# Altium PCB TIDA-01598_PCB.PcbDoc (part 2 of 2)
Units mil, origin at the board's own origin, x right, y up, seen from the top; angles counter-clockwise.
Board outline 5000 x 4300 mil, 4 copper layers (Top Layer, Power, Ground, Bottom Layer), stack 61.6 mil thick; 99 components, 31 nets, 235 pads, 61 vias.
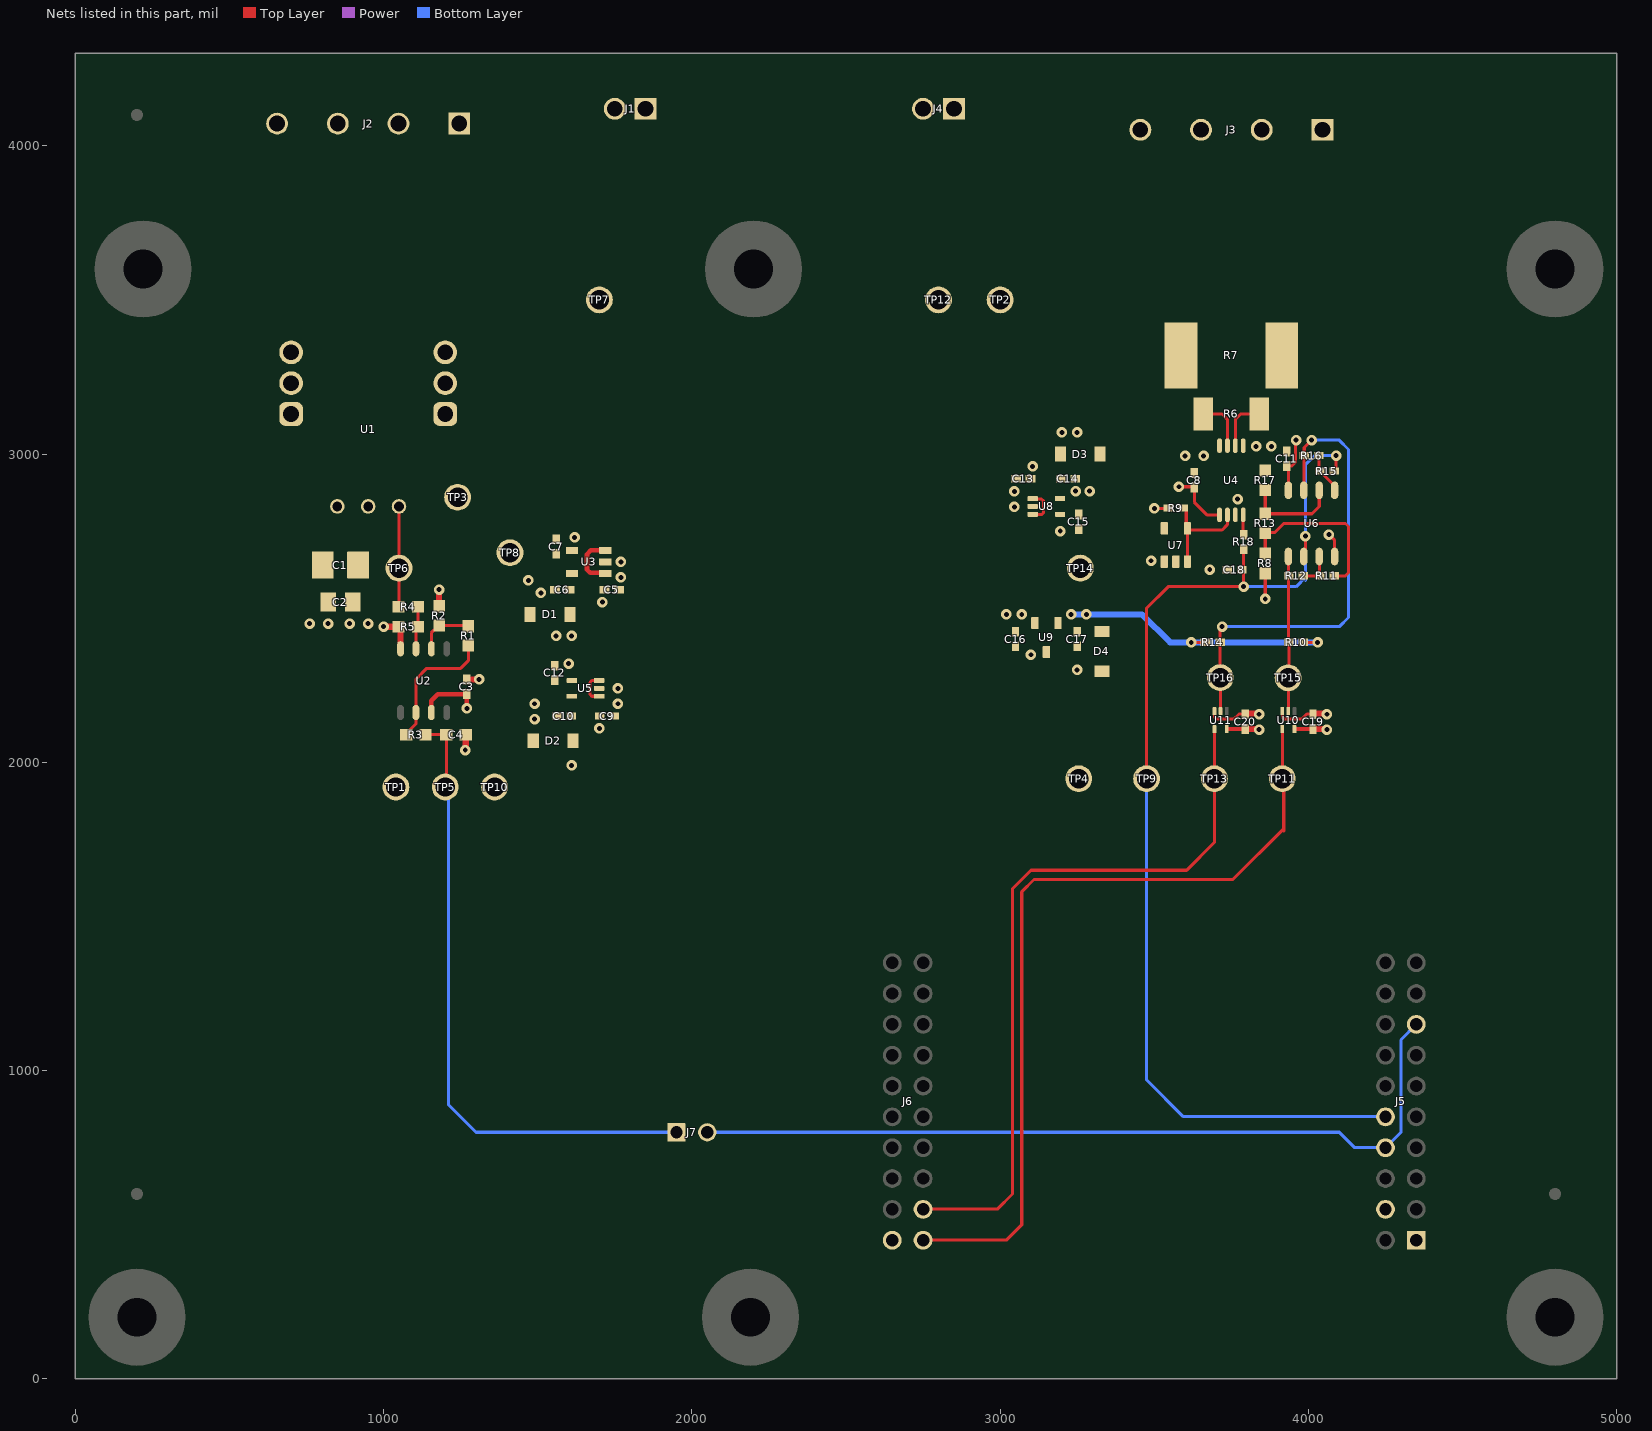
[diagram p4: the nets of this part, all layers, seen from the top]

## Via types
v1: diameter 34, hole 16, Top Layer to Bottom Layer, tented top, 61 vias

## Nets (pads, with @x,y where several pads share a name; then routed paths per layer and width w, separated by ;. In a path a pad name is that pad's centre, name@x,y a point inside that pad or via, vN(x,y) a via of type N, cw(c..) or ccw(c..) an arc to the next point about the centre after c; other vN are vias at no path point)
3V3_DIG: C17.1 D4.1 J5.1 R10.2 R14.2 U9.1 | length 939.2
  Top Layer w10: v1(3620,2388.9) R14.2@3666.38,2388.9 ; R10.2@3983.62,2388.9 v1(4030,2388.9)
  Power w10: v1(4030,2388.9) v1@4040,2388.9
  Bottom Layer w20: v1@3230,2475 3235,2480 v1(3280,2480) 3460,2480 3551.1,2388.9 v1(3620,2388.9) ; v1@3625,2385 3628.9,2388.9 v1(4030,2388.9)
  other v1: 3230,2480
3V3_HALL: C3.1 C10.1 D2.1 TP10.1 U2.7 U5.5 | length 205.2
  Top Layer w15: U2.7@1155,2165 1155,2200 1176.38,2221.38 C3.1@1270,2221.38 v1(1270,2175)
  other v1: 1610,1990
3V3_INA: C8.1 C11.1 C14.1 C19.1 C20.1 D3.1 R8.2 R9.2 TP14.1 U4.5 U6.8 U8.5 U10.5 U11.5 | length 733.8
  Top Layer w10: v1(3500,2823.9) R9.2@3556.38,2823.9 ; v1(3580,2893.9) 3626.38,2893.9 3630,2890.28 3630,2843.9 3672.2,2801.69 U4.5@3711.61,2801.69 ; v1(3860,2530) R8.2@3860,2613.5 R8.2@3860,2615 ; U6.8@3935,2882.28 3935,2956.38 C11.1@3930,2961.38 3946.38,2961.38 3957.76,2972.76 3957.76,3042.76 v1(3960,3045)
  Top Layer w12: U11.5@3734.69,2107.87 3794.13,2107.87 C20.1@3795,2107 ; U10.5@3954.69,2107.87 4014.13,2107.87 C19.1@4015,2107
  Top Layer w20: C20.1@3795,2108.38 v1@3838.62,2108.38 ; C19.1@4015,2108.38 v1@4058.62,2108.38
  other v1: 3840,2105.9 4060,2105.9 3200,3070 3250,3070
5V_HALL: C1.1 C2.1 C6.1 D1.1 TP8.1 U1.9 U3.5
  other v1: 1560,2410 1610,2410 760,2450 820,2450
6V_HALL_VIN: C5.1 C9.1 J1.2 TP7.1 U3.1 U3.3 U5.1 U5.3 | length 281.9
  Top Layer w10: U5.1@1699.29,2214.41 1675.59,2214.37 1669.68,2220.28 1669.68,2259.65 1675.59,2265.56 U5.3@1699.29,2265.59
  Top Layer w15: U3.3@1719.13,2687.4 1672.4,2687.4 1660,2675 1660,2625 1670,2615 U3.1@1720,2615
  other v1: 1700,2109.96 1710,2519.96
6V_VIN: C13.1 C16.1 J4.2 TP12.1 U8.1 U8.3 U9.2 | length 110.5
  Top Layer w10: U8.3@3107.09,2803.31 3134.41,2803.31 3140,2808.9 3140,2848.9 3134.41,2854.49 U8.1@3107.09,2854.49
  other v1: 3020,2480 3070,2480 3105,2960
GND: C1.2 C2.2 C3.2 C4.2 C5.2 C6.2 C7.2 C8.2 C9.2 C10.2 C11.2 C12.2 C13.2 C14.2 C15.2 C16.2 C17.2 C18.2 C19.2 C20.2 D1.2 D2.2 D3.2 D4.2 J1.1 J4.1 J5.22 J6.20 R2.1 R5.1 R17.2 TP1.1 TP2.1 TP3.1 TP4.1 U1.8 U2.4 U3.2 U4.1 U4.4 U4.7 U5.2 U6.4 U7.1 U7.2 U7.5 U8.2 U9.3 U10.3 U11.3 | length 727.5
  Top Layer w10: U11.3@3695.31,2166.13 3695.31,2146.68 3701.93,2140.07 3758.07,2140.07 3775,2157 C20.2@3795,2157 ; U10.3@3915.31,2166.13 3915.31,2146.68 3921.93,2140.07 3978.07,2140.07 3995,2157 C19.2@4015,2157 ; v1(4066.42,2738.62) 4085,2720 U6.4@4085,2667.72
  Top Layer w20: v1(1000,2440) R5.1@1048.5,2440 ; R5.1@1050,2440 1055,2435 U2.4@1055,2368.35 ; R2.1@1180,2506.5 v1(1180,2560) ; v1@1266.5,2041.5 C4.2@1266.5,2090 ; C3.2@1269,2269 v1(1310,2269) ; C3.2@1270,2268.62 v1@1308.62,2268.62 ; C20.2@3795,2158.38 v1@3838.62,2158.38 ; C19.2@4015,2158.38 v1@4058.62,2158.38
  other v1: 1265,2040 1490,2140 3840,2155.9 4060,2155.9 1490,2190 1760,2189.96 1760,2239.96 3250,2300 1600,2319.96 3100,2348.9 890,2450 950,2450 1510,2550 1470,2590 1770,2599.96 3680,2625 1770,2649.96 3490,2653.9 1620,2729.96 3195,2750 3046.38,2828.9 3770,2853.9 3046.38,2878.9 3245,2880 3290,2880 3600,2993.9 3660,2993.9 3830,3025 3880,3025
NetC7_1: C7.1 U3.4
NetC12_1: C12.1 U5.4
NetC15_1: C15.1 U8.4
NetJ2_1: J2.1 J2.2 U1.4 U1.5 U1.6
NetJ2_3: J2.3 J2.4 U1.1 U1.2 U1.3
NetJ3_1: J3.1 J3.2 R6.2 R7.2 U4.2 | length 170.5
  Top Layer w10: U4.2@3762.8,3027.2 3762.8,3112.8 3780,3130 R6.2@3840.55,3130
NetJ3_3: J3.3 J3.4 R6.1 R7.1 U4.3 | length 170.5
  Top Layer w10: R6.1@3659.45,3130 3720,3130 3737.2,3112.8 U4.3@3737.2,3027.2
NetJ5_8: J5.8 J5.24 J7.2 | length 2662.1
  Bottom Layer w10: J7.2@2050,800 4100,800 4150,750 J5.24@4250,750 4300,800 4300,1100 J5.8@4350,1150
NetR1_1: R1.1 R2.2 U2.2 | length 170.6
  Top Layer w10: U2.2@1155,2368.35 1155,2420 R2.2@1175,2440 ; R2.2@1180,2443.5 1268.5,2443.5 R1.1@1270,2445
NetR1_2: R1.2 R3.1 U2.6 | length 432.4
  Top Layer w10: R3.1@1075,2090 1075,2095 1105,2125 U2.6@1105,2161.65 ; U2.6@1105,2165 1105,2270 1140,2305 1250,2305 1275,2330 R1.2@1275,2378.5
NetR4_1: R4.1 TP6.1 U1.7 | length 337.1
  Top Layer w10: R4.1@1045,2495 1050,2500 TP6.1@1050,2630 U1.7@1050,2830
NetR4_2: R4.2 R5.2 U2.3 | length 139.3
  Top Layer w10: U2.3@1105,2368.35 1105,2435 1111.5,2441.5 R4.2@1111.5,2505
NetR8_1: R8.1 R11.1 R13.2 | length 564.2
  Top Layer w10: R8.1@3860,2670 R8.1@3860,2676.5 R13.2@3860,2743.5 ; R13.2@3860,2745 3890,2745 3920,2775 4120,2775 4130,2765 4130,2615 4120,2605 R11.1@4083.62,2605 R11.1@4080,2605
NetR9_1: R9.1 U4.6 U7.3 U7.4 | length 344.9
  Top Layer w10: R9.1@3603.62,2823.9 3603.62,2761.81 U7.4@3607.4,2758.03 ; U7.3@3607.4,2649.76 U7.3@3607.4,2650.87 U7.4@3607.4,2758.03 ; U4.6@3737.2,2801.69 3737.2,2771.1 3720,2753.9 3611.54,2753.9 U7.4@3607.4,2758.03
NetR10_1: R10.1 R12.2 TP15.1 U6.1 U10.2 | length 532.9
  Top Layer w10: TP15.1@3931,2271 3935,2267 U10.2@3935,2166.13 ; U10.2@3935,2162 U10.2@3935.91,2162.91 ; R10.1@3935,2385 U6.1@3935,2667.72 U6.1@3935,2677.72 ; R10.1@3935.91,2389.53 R10.1@3936.38,2390 3936.38,2260.62 TP15.1@3938,2259
NetR11_2: R11.2 R12.1 U6.3 | length 116
  Top Layer w10: R12.1@3983.62,2605 R11.2@4036.38,2605 4036.38,2666.34 U6.3@4035,2667.72
NetR13_1: R13.1 R17.1 U6.6 | length 312.5
  Top Layer w10: R17.1@3860,2882.01 R13.1@3860,2806.5 4011.5,2806.5 4035,2830 U6.6@4035,2882.28
NetR14_1: R14.1 R16.2 TP16.1 U6.7 U11.2 | length 1567.9
  Top Layer w10: TP16.1@3706,2261 3713.62,2268.62 R14.1@3713.62,2390 3713.62,2433.62 v1(3720,2440) ; U11.2@3715,2162 U11.2@3715.91,2162.91 ; U11.2@3715,2166.13 TP16.1@3715,2272 ; U6.7@3985,2882.28 R16.2@3985,2993.62 ; R16.2@3986.38,2995 3986.38,3021.38 v1(4010,3045)
  Bottom Layer w10: v1@3715,2440 v1(3720,2440) 4100,2440 4130,2470 4130,3015 4100,3045 v1(4010,3045)
NetR15_2: R15.2 R16.1 U6.5 | length 134
  Top Layer w10: R16.1@4033.62,2995 4033.62,2947.76 R15.2@4036.38,2945 4085,2896.38 U6.5@4085,2882.28
NetR18_1: R18.1 U4.8 | length 64.8
  Top Layer w10: U4.8@3788.39,2802.8 3788.39,2740.24 R18.1@3790,2738.62
OUT_A: J6.40 TP11.1 U10.4 | length 2691
  Top Layer w10: J6.40@2750,450.86 2750.86,450 3020,450 3070,500 3070,1580 3110,1620 3755,1620 3920,1785 ; TP11.1@3915,1942 3915.31,1942.32 U10.4@3915.31,2107.87 ; 3920,1778 3920,1785 ; TP11.1@3920,1947 3920,1785
OUT_B: J6.39 TP13.1 U11.4 | length 2390.5
  Top Layer w10: J6.39@2750,550.86 2990.86,550.86 3040,600 3040,1590 3100,1650 3605,1650 3695,1740 TP13.1@3695,1942 ; TP13.1@3695,1947 TP13.1@3695,1942 ; U11.4@3695.31,2107.87 3695.31,1942.32 TP13.1@3695,1942
OUT_HALL: C4.1 J7.1 R3.2 TP5.1 | length 2050.5
  Top Layer w10: R3.2@1136.5,2090 1200,2090 C4.1@1203.5,2086.5 ; TP5.1@1198.5,1921.46 TP5.1@1200,1919.96 ; TP5.1@1200,1925 1203.5,1928.5 C4.1@1203.5,2086.5 ; C4.1@1203.5,2090 C4.1@1203.5,2086.5 ; C4.1@1205,2085 C4.1@1203.5,2086.5
  Bottom Layer w10: TP5.1@1200,1919.96 1210,1909.96 1210,890 1300,800 J7.1@1950,800
OUT_INA: C18.1 J5.25 R15.1 R18.2 TP9.1 U6.2 | length 3641.9
  Top Layer w10: TP9.1@3474,1940 3475,1941 3475,2500 3545,2570 v1(3790,2570) R18.2@3790,2691.38 ; U6.2@3990,2675 v1(3990,2733.9) ; R15.1@4080,2945 4090,2955 v1(4090,2995)
  Bottom Layer w10: TP9.1@3477,1948 3475,1946 3475,970 3594.14,850.86 J5.25@4250,850.86 ; v1(3790,2570) 3960,2570 3990,2600 ; 3990,2590 3990,2600 ; v1(4090,2995) 4020,2995 3990,2965 3990,2600
pads on no net: FID1.1 FID2.1 FID3.1 H1.1 H2.1 H3.1 H4.1 H5.0 H6.0 H7.0 H8.0 H9.1 H10.0 H11.1 H12.0 J5.2 J5.3 J5.4 J5.5 J5.6 J5.7 J5.9 J5.10 J5.21 J5.23 J5.26 J5.27 J5.28 J5.29 J5.30 J6.11 J6.12 J6.13 J6.14 J6.15 J6.16 J6.17 J6.18 J6.19 J6.31 J6.32 J6.33 J6.34 J6.35 J6.36 J6.37 J6.38 U2.1 U2.5 U2.8 U10.1 U11.1

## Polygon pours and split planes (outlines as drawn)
NetJ2_1 on Top Layer "TOP_LAYER_NETJ2_1_P134" (solid, remove dead copper, pour order 134): 999.96,4239.96 1445.04,4239.96 1470,4215 1470,3075 1444.96,3049.96 995.04,3049.96 960,3085 960,4200
NetJ2_3 on Top Layer "TOP_LAYER_NETJ2_3_P132" (solid, remove dead copper, pour order 132): 940,4215 940,3085 904.96,3049.96 485.04,3049.96 455,3080 455,4210 484.96,4239.96 915.04,4239.96
GND on Top Layer "TOP_LAYER_GND_P122" (solid, remove dead copper, pour order 122): 910,2800 910,2870 980,2870 980,2430 870,2430 870,2760
5V_HALL on Top Layer "TOP_LAYER_5V_HALL_P120" (solid, remove dead copper, pour order 120): 850,2430 850,2760 880,2790 880,2870 810,2870 740,2800 740,2430
GND on Top Layer "TOP_LAYER_GND_P108" (solid, remove dead copper, pour order 108): 3740,2873.9 3750,2883.9 3790,2883.9 3800,2873.9 3800,2773.9 3740,2773.9
GND on Top Layer "TOP_LAYER_GND_P106" (solid, remove dead copper, pour order 106): 3921.1,3053.9 3950,3025 3950,2985 3900,2985 3880,2965 3880,2925 3830,2925 3830,2945 3780,2993.9 3780,3053.9
GND on Top Layer "TOP_LAYER_GND_P102" (solid, remove dead copper, pour order 102): 3660,2604.5 3756.77,2604.5 3756.77,2644.5 3660,2644.5
GND on Top Layer "TOP_LAYER_GND_P096" (solid, remove dead copper, pour order 96): 3580,2625 3580,2775 3570,2785 3470,2785 3460,2775 3460,2635 3470,2625
GND on Top Layer "TOP_LAYER_GND_P092" (solid, remove dead copper, pour order 92): 3720,3045 3720,2935 3710,2925 3590,2925 3580,2935 3580,3045 3590,3055 3710,3055
6V_VIN on Top Layer "TOP_LAYER_6V_VIN_P090" (solid, remove dead copper, pour order 90): 3140,2420 3140,2490 3130,2500 3010,2500 3000,2490 3000,2420 3010,2410 3130,2410
3V3_DIG on Top Layer "TOP_LAYER_3V3_DIG_P088" (solid, remove dead copper, pour order 88): 3360,2410 3170,2410 3160,2420 3160,2490 3170,2500 3350,2500 3360,2490
GND on Top Layer "TOP_LAYER_GND_P086" (solid, remove dead copper, pour order 86): 3030,2400 3020,2390 3020,2340 3030,2330 3220,2330 3220,2280 3230,2270 3360,2270 3370,2280 3370,2370 3340,2400
GND on Top Layer "TOP_LAYER_GND_P084" (solid, remove dead copper, pour order 84): 3276.38,2778.9 3176.38,2778.9 3176.38,2728.9 3276.38,2728.9
GND on Top Layer "TOP_LAYER_GND_P082" (solid, remove dead copper, pour order 82): 3230,3030 3220,3020 3220,2870 3230,2860 3340,2860 3350,2870 3350,3030
GND on Top Layer "TOP_LAYER_GND_P080" (solid, remove dead copper, pour order 80): 3026.38,2798.9 3026.38,2938.9 3126.38,2938.9 3126.38,2798.9
NetC15_1 on Top Layer "TOP_LAYER_NETC15_1_P002" (solid, remove dead copper, pour order 2): 3170,2778.9 3276.38,2778.9 3276.38,2828.9 3236.38,2828.9 3226.38,2818.9 3170,2818.9
6V_VIN on Top Layer "TOP_LAYER_6V_VIN_P078" (solid, remove dead copper, pour order 78): 3126.38,2838.9 3086.38,2838.9 3086.38,2978.9 3126.38,2978.9
3V3_INA on Top Layer "TOP_LAYER_3V3_INA_P076" (solid, remove dead copper, pour order 76): 3210,2840 3170,2840 3170,3080 3180,3090 3270,3090 3280,3080 3280,3060 3270,3050 3220,3050 3210,3040
GND on Top Layer "TOP_LAYER_GND_P074" (solid, remove dead copper, pour order 74): 1530,2289.96 1630,2289.96 1630,2339.96 1530,2339.96
GND on Top Layer "TOP_LAYER_GND_P072" (solid, remove dead copper, pour order 72): 1580,2049.96 1580,2200 1570.04,2209.96 1469.96,2209.96 1460,2200 1460,2040 1570.04,2040
GND on Top Layer "TOP_LAYER_GND_P070" (solid, remove dead copper, pour order 70): 1780,2259.96 1780,2140 1770,2130 1680,2129.96 1680,2269.96 1770,2269.96
NetC12_1 on Top Layer "TOP_LAYER_NETC12_1_P068" (solid, remove dead copper, pour order 68): 1630,2289.96 1530,2289.96 1530,2239.96 1570,2239.96 1580,2249.96 1630,2249.96
6V_HALL_VIN on Top Layer "TOP_LAYER_6V_HALL_VIN_P066" (solid, remove dead copper, pour order 66): 1680,2229.96 1720,2229.96 1720,2089.96 1680,2089.96
3V3_HALL on Top Layer "TOP_LAYER_3V3_HALL_P064" (solid, remove dead copper, pour order 64): 1590,2229.96 1630,2230 1640,2220 1640,1980 1630,1970 1590,1970
5V_HALL on Top Layer "TOP_LAYER_5V_HALL_P004" (solid, remove dead copper, pour order 4): 1589.96,2629.96 1630,2629.96 1630,2390 1540,2390 1540,2430 1580,2430 1580,2620
NetC7_1 on Top Layer "TOP_LAYER_NETC7_1_P014" (solid, remove dead copper, pour order 14): 1640,2699.96 1540,2699.96 1540,2649.96 1580,2649.96 1590,2659.96 1640,2659.96
GND on Top Layer "TOP_LAYER_GND_P022" (solid, remove dead copper, pour order 22): 1560,2450 1570.2,2460 1570.2,2599.8 1560,2610 1450,2610 1450,2450
GND on Top Layer "TOP_LAYER_GND_P062" (solid, remove dead copper, pour order 62): 1540,2699.96 1640,2699.96 1640,2749.96 1540,2749.96
GND on Top Layer "Bottom Layer-No Net" (solid, remove dead copper, pour order 140): 1700,2665 1750,2665 1765,2680 1800,2680 1805,2675 1805,2545 1800,2540 1750,2540 1745,2545 1745,2630 1740,2635 1700,2635 1695,2640 1695,2660 1700,2665
6V_HALL_VIN on Top Layer "Bottom Layer-No Net" (solid, remove dead copper, pour order 142): 1740,2625 1690,2625 1685,2620 1685,2500 1690,2495 1730,2495 1735,2500 1735,2620 1740,2625
NetJ3_3 on Top Layer "Bottom Layer-No Net" (solid, remove dead copper, pour order 144): 3740,3650 3690,3600 3690,3165 3690,3080 3685,3075 3395,3075 3265,3205 3150,3320 3150,3830 3150,4200 3180,4230 3710,4230 3740,4200 3740,3650
NetJ3_1 on Top Layer "Bottom Layer-No Net" (solid, remove dead copper, pour order 146): 3760,3650 3810,3600 3810,3080 3815,3075 4315,3075 4335,3095 4350,3110 4350,3165 4350,4205 4320,4235 3780,4235 3760,4215 3760,3650
GND on Ground "GROUND_GND_P006" (solid, remove dead copper, pour order 6): 80,4300 4910,4300 5000,4210 5000,270 4730,0 270,0 0,270 0,4220
3V3_HALL on Power "POWER_3V3_HALL_P126" (solid, remove dead copper, pour order 126): 1640,1875 1640,2330 1620.04,2349.96 864.96,2349.96 850,2335 850,1885 875,1860 1625,1860
5V_HALL on Power "POWER_5V_HALL_P118" (solid, remove dead copper, pour order 118): 1640,2755 1640,2400 1629.96,2389.96 675.04,2389.96 650,2415 650,2730 675,2755
6V_HALL_VIN on Power "POWER_6V_HALL_VIN_P012" (solid, remove dead copper, pour order 12): 1920,4230 1660,4230 1650,4220 1650,2000 1660,1990 1920,1990 1930,2000 1930,4220
3V3_DIG on Power "POWER_3V3_DIG_P136" (solid, remove dead copper, pour order 136): 3160,2488.9 3160,2500 3170,2510 3340,2510 3350,2500 3350,595 3365,580 4420,580 4430,570 4430,340 4420,330 3205,330 3160,375
6V_VIN on Power "POWER_6V_VIN_P138" (solid, remove dead copper, pour order 138): 2925,4230 2675,4230 2660,4215 2660,2010 2680,1990 3120,1990 3140,2010 3140,3080 3120,3100 2960,3100 2940,3120 2940,4215
3V3_INA on Power "Bottom Layer-No Net" (solid, remove dead copper, pour order 148): 3185,3100 3170,3100 3160,3090 3160,2555 3185,2530 3390,2530 3415,2505 3415,2094 3458,2051 4108,2051 4160,2103 4160,2530 4160,3080 4140,3100

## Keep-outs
Keep-Out Layer:
  text ".Layer_Name" at 577,-858.49 h60

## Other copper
Top Layer:
  text ".Layer_Name" at 577,-858.49 h60
Bottom Layer:
  text ".Layer_Name" at 577,-858.49 h60

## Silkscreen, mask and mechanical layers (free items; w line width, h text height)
Top Overlay:
  region: 100,3200 100,2900 200,2900 200,3200
  lines w5: 3720,2490 3820,2490 3820,2706 ; 3820,2705 3830,2715
  lines w10: 550,3648.86 550,3750 550,3865 ; 550,3650 1350,3650 ; 550,3748.86 1350,3748.86 ; 950,3750 950,3865 ; 1350,3648.86 1350,3750 1350,3865 ; 1800,3650 1800,3990 ; 1910,3991.1 1910,3650 1690,3650 ; 2800,3650 2800,3990 ; 2910,3991.1 2910,3650 2690,3650 ; 3350,3628.9 3350,3728.9 ; 3350,3630 4150,3630 ; 3350,3845 3350,3730 4150,3730 4150,3845 ; 3470,2740 3470,2580 4140,2580 4140,2640 ; 3470,2810 3470,3430 ; 3475,3430 4140,3430 4140,2740 ; 3750,3730 3750,3845 ; 1350,3748.86 1350,3748.86 ; 1690,3650 1690,3991.1 1591.1,3991.1 1590,3990 1590,3650 1690,3650 ; 2690,3650 2590,3650 2590,3990 2591.1,3991.1 2690,3991.1 2690,3650 ; 4150,3628.9 4150,3628.9 ; 4150,3628.9 4150,3728.9 ; 4150,3728.9 4150,3728.9 ; 650,2020 650,3630 1320,3630 1320,2020 650,2020
  text "HALL HIGH" at 590,3790 h72.83
  text "HALL LOW" at 990,3790 h72.83
  text "INA LOW" at 3420,3770 h72.83
  text "INA HIGH" at 3810,3770 h72.83
  text "Supply" at 1650,3740 h72.83 r90
  text "GND IN" at 1870,3740 h72.83 r90
  text "Supply" at 2650,3740 h72.83 r90
  text "GND IN" at 2870,3740 h72.83 r90
  text "5V-7V IN" at 1770,3700 h72.83 r90
  text "5V-7V IN" at 2770,3700 h72.83 r90
  text "15A Max Passthrough" at 640,3680 h72.83
  text "15A Max Passthrough" at 3440,3660 h72.83
  text "TIDA-01598" at 4800,1850 h108.27 r90
  text ".Layer_Name" at 577,-858.49 h60
Bottom Overlay:
  text ".Layer_Name" at 577,-858.49 h60
Top Paste:
  text ".Layer_Name" at 577,-858.49 h60
Bottom Paste:
  text ".Layer_Name" at 577,-858.49 h60
Top Solder:
  text ".Layer_Name" at 577,-858.49 h60
  text ".Layer_Name" at 577,-858.49 h60
Bottom Solder:
  text ".Layer_Name" at 577,-858.49 h60
Drill Guide:
  text ".Layer_Name" at 577,-858.49 h60
M1 Board Outline:
  the board outline again, w10
  text ".Layer_Name" at 577,-858.49 h60
M2 Board Dimensions:
  rectangle: 0,-275 125,-150
  rectangle: 125,-400 500,-275
  lines w7: 0,-275 1000,-275 ; 125,-400 125,-150 ; 250,-400 250,-150 ; 500,-400 500,-150 ; 750,-400 750,-150 ; 0,-400 1000,-400 1000,-150 0,-150 0,-400
  text ".Layer_Name" at 577,-858.49 h60
M3 3D STEP Top:
  text ".Layer_Name" at 577,-858.49 h60
M4 3D STEP Bottom:
  text ".Layer_Name" at 577,-858.49 h60
M5 Assembly Top:
  circle w10: c1680,2610 r5
  circle w10: c1710,2215 r5
  circle w10: c3091,2855 r3.16
  circle w10: c3111,2474 r8.25
  circle w10: c3533,2631 r6
  circle w10: c3735,2352 r3
  circle w10: c3956,2353 r6.08
  lines w10: -292,-930.17 6308,-930.17 ; -292,-726.83 6310,-726.83 ; -292,-523.5 -292,-1133.5 3713,-1133.5 6310,-1133.5 6310,-523.5 -291.5,-523.5 -291.5,-1133.5 1284,-1133.5 ; 2173,-1133.5 2173,-523.5 ; 3440,-726.83 3440,-523.5 ; 4280,-726.83 4280,-523.5 ; 4902,-1140 4902,-937.17
  text "COMPONENTS MARKED 'DNP' SHOULD NOT BE POPULATED." at 1153.5,-318.5 h25
  text "ASSEMBLY VARIANT:" at 1153,-434 h25
  text ".VariantName" at 2189,-434 h25
  text "PCB VIEWED FROM TOP SIDE" at -228.5,-655.67 h25
  text "BOARD #:" at 2248,-655.67 h25
  text ".PRJ_Number" at 2793.5,-655.67 h25
  text "REV:" at 3638,-655.67 h25
  text ".PCB_Rev" at 3929.5,-655.67 h25
  text "SVN REV:" at 4476,-655.67 h25
  text ".VersionControl_RevNumber" at 4982,-655.67 h25
  text "TID #:" at 2248,-859 h25
  text ".TID" at 2793.5,-859 h25
  text "PLOT NAME =" at -228.5,-1064.34 h25
  text ".plot_File_Name" at 577,-1064.34 h25
  text "GENERATED    :" at 2250,-1064.34 h25
  text ".Print_Date" at 3119.5,-1064.34 h25
  text ".Print_Time" at 3848.5,-1064.34 h25
  text "TEXAS INSTRUMENTS" at 5113,-1064.34 h25
M6 Assembly Bottom:
  lines w10: -292.5,-727.33 6309.5,-727.33 ; -290.5,-930.67 6309.5,-930.67 ; 1115.5,-1140.5 1115.5,-937.67 ; 1737.5,-727.33 1737.5,-524 ; 2577.5,-727.33 2577.5,-524 ; 3844.5,-1134 3844.5,-524 ; 4733.5,-1134 6309,-1134 6309,-524 -292.5,-524 -292.5,-1134 2304.5,-1134 6309.5,-1134 6309.5,-524
  text "COMPONENTS MARKED 'DNP' SHOULD NOT BE POPULATED." at 6102,-318 h60
  text ".VariantName" at 5058,-434 h60
  text "ASSEMBLY VARIANT:" at 6097,-434 h60
  text ".VersionControl_RevNumber" at 1035.5,-656.17 h60
  text "SVN REV:" at 1541.5,-656.17 h60
  text ".PCB_Rev" at 2088,-656.17 h60
  text "REV:" at 2379.5,-656.17 h60
  text ".PRJ_Number" at 3224,-656.17 h60
  text "BOARD #:" at 3769.5,-656.17 h60
  text "PCB VIEWED FROM BOTTOM SIDE" at 6246,-656.17 h60
  text ".TID" at 3224,-859.5 h60
  text "TID #:" at 3769.5,-859.5 h60
  text "TEXAS INSTRUMENTS" at 904.5,-1064.84 h60
  text ".Print_Time" at 2169,-1064.84 h60
  text ".Print_Date" at 2898,-1064.84 h60
  text "GENERATED    :" at 3767.5,-1064.84 h60
  text ".plot_File_Name" at 5440.5,-1064.84 h60
  text "PLOT NAME =" at 6246,-1064.84 h60
M9 Title Sheet:
  drawing of 57 lines, arcs and shapes, not listed
  text "1" at 739.84,8036.5 h70
  text "2" at 3235.5,8036.5 h70
  text "3" at 5724.84,8036.5 h70
  text "4" at 8231.51,8036.5 h70
  text "5" at 10730.5,8036.5 h70
  text "6" at 13235.5,8036.5 h70
  text "A" at -416.5,6893.5 h70
  text "A" at 14383.5,6893.5 h70
  text "B" at -416.5,4513.5 h70
  text "B" at 14383.5,4513.5 h70
  text "C" at -416.5,2138.5 h70
  text "C" at 14383.5,2138.5 h70
  text "PROJECT TITLE:" at 11343.5,277.5 h45
  text ".PRJ_Title" at 11393.5,144.17 h70
  text "DESIGNED FOR:" at 11343.5,-23.5 h45
  text ".PRJ_Customer" at 11393.5,-163.5 h70
  text "D" at -416.5,-231.5 h70
  text "D" at 14383.5,-231.5 h70
  text "FILE NAME:" at 11343.5,-323.5 h45
  text ".PCB_File_Name_No_Path" at 11393.5,-443.5 h70
  text "Texas Instruments (TI) and/or its licensors do not warrant the accuracy or completeness of this specification" at 6374,-605.34 h45
  text "ENGINEER:" at 11343.5,-613.5 h45
  text "LAYOUT BY:" at 12848.5,-613.5 h45
  text "or any information contained therein. TI and/or its licensors do not warrant that this design will meet" at 6329.01,-718 h45
  text ".PRJ_Engineer" at 11393.5,-768.49 h70
  text ".PCB_Layout" at 12899,-768.49 h70
  text "the specifications, will be suitable for your application or fit for any particular purpose, or will operate in" at 6329.01,-830.67 h45
  text ".Layer_Name" at 577,-858.49 h60
  text "ALTIUM DESIGNER VERSION:" at 12848.5,-923.5 h45
  text "an implementation. TI and/or its licensors do not warrant that the design is production worthy. You should" at 6329.01,-943.33 h45
  text "completely validate and test your design implementation to confirm the system functionality for your application." at 6374,-1056 h45
  text ".print_Scale" at 11393.5,-1056.83 h70
  text ".Application_BuildNumber" at 12899,-1056.83 h70
  text "1" at 739.84,-1263.5 h70
  text "2" at 3235.5,-1263.5 h70
  text "3" at 5724.84,-1263.5 h70
  text "4" at 8231.51,-1263.5 h70
  text "5" at 10730.5,-1263.5 h70
  text "6" at 13235.5,-1263.5 h70
M10 Fab Notes:
  drawing of 189 lines, arcs and shapes, not listed
  text "DESIGN INFORMATION" at 12382.02,6356.17 h60
  text "MIN. TRACK WIDTH:" at 11737.46,6224.05 h60
  text "8" at 12833.7,6224.05 h60
  text "MIL" at 12988.46,6224.05 h60
  text "MIN. CLEARANCE:" at 11737.46,6099.92 h60
  text "0.2" at 12773.7,6099.93 h60
  text "mm" at 12988.46,6099.92 h60
  text "MIN. VIA PAD SIZE:" at 11737.46,5975.8 h60
  text "24" at 12803.71,5975.8 h60
  text "MIL" at 12988.46,5975.8 h60
  text "0.05mm (2MIL)" at 12432.46,5845.9 h60
  text "MINIMUM ANNULAR RING" at 11408.23,5837.67 h60
  text "EXTERNAL" at 13140.46,5837.67 h60
  text "PER" at 11608.23,5727.55 h60
  text "IPC-D-275 CLASS 2 LEVEL C" at 11828.23,5727.54 h60
  text "MIL, HOLES" at 13316.46,5627.07 h60
  text "+/-" at 12924,5618.48 h60
  text "+/-" at 13778,5618.48 h60
  text "REGISTRATION TOLERANCES:" at 11408.23,5617.42 h60
  text "METAL" at 12608,5617.42 h60
  text "5" at 13184.2,5617.42 h60
  text "3" at 14017.2,5617.42 h60
  text "MIL" at 14133.46,5617.42 h60
  text "HOLE SIZE TOLERANCE (UNLESS OTHERWISE SPECIFIED):" at 11408.23,5519.1 h60
  text "+/-" at 13778,5516.23 h60
  text "3" at 14017.2,5515.17 h60
  text "MIL" at 14133.46,5515.17 h60
  text "MATERIAL:" at 11333.46,5377.52 h60
  text "FR-4 High Tg" at 12319.9,5249 h60
  text "X" at 12175.46,5241.01 h60
  text "FR-408" at 11754.46,5236.49 h60
  text "OTHER" at 13242.46,5236.49 h60
  text "62 MIL (1.6mm) +/-10%" at 12074.56,5093.46 h60
  text "X" at 11954.46,5091.01 h60
  text "THICKNESS:" at 11408.23,5085.24 h60
  text "OTHER" at 13359.46,5085.24 h60
  text "TOLERANCE:" at 11408.23,4946.92 h60
  text "X" at 12256.46,4946.92 h60
  text "ANSI IPC-6012 TYPE 3 CLASS 2" at 12434.48,4946.92 h60
  text "OTHER +/-" at 12434.46,4802.73 h60
  text "BOW & TWIST:" at 11408.23,4657.54 h60
  text "X" at 12256.46,4657.54 h60
  text "ANSI IPC-6012 TYPE 3 CLASS 2" at 12434.48,4657.54 h60
  text "OTHER +/-" at 12434.46,4510.85 h60
  text "DRILLING:" at 11333.46,4380.23 h60
  text "NC_DRILL FILES" at 13094.46,4275.04 h60
  text "REFERENCE:" at 11408.23,4271.1 h60
  text "X" at 12065.46,4271.01 h60
  text "AS SHOWN" at 12243.46,4271.1 h60
  text "X" at 12966.46,4271.1 h60
  text "OTHER" at 13392.46,4128.85 h60
  text "PTH COPPER THICKNESS:" at 11407.91,4125.32 h60
  text "X" at 12547.14,4125.32 h60
  text "20-30 um" at 12675.14,4125.32 h60
  text "BOARD FINISH:" at 11333.46,3977.73 h60
  text "SILKSCREEN:" at 11488.68,3867.6 h60
  text "X" at 12446.46,3867.6 h60
  text "TOP" at 12563.46,3867.6 h60
  text "X" at 12956.46,3867.6 h60
  text "BOTTOM" at 13074.46,3867.6 h60
  text "SILKSCREEN COLOR:" at 11488.68,3712.41 h60
  text "X" at 12445.46,3712.41 h60
  text "WHITE" at 12563.46,3712.41 h60
  text "OTHER" at 13074.46,3712.41 h60
  text "X" at 12576.46,3568.96 h60
  text "GREEN" at 12694.46,3568.96 h60
  text "OTHER" at 13312.46,3568.96 h60
  text "SOLDER RESIST COLOR:" at 11488.68,3562.1 h60
  text "X" at 12576.46,3414.71 h60
  text "MATTE" at 12694.46,3414.71 h60
  text "SEMI-GLOSS" at 13312,3414.07 h60
  text "IMMERSION GOLD (ENIG)" at 12394.46,3241.94 h60
  text "ENEPIG" at 13732,3234.72 h60
  text "SURFACE FINISH:" at 11333.46,3233.72 h60
  text "X" at 12216.46,3233.72 h60
  text "IMM. TIN/SILVER OR EQUIV" at 11663,3096.4 h60
  text "OTHER" at 13094.46,3092.47 h60
  text "ARRAY/PANEL:" at 11333.46,2937.09 h60
  text "CUT AND TRIM PER M1 BOARD OUTLINE" at 12394.46,2928.87 h60
  text "N.C. ROUTE" at 12394.46,2792.9 h60
  text "X" at 13082.46,2792.9 h60
  text "V. SCORE" at 13260.46,2792.9 h60
  text "CERTIFICATION:" at 11333.46,2663.77 h60
  text "MATERIALS AND WORKMANSHIP FOR ALL PCBS" at 12058.46,2663.77 h60
  text "TO MEET OR EXCEED THE REQUIREMENTS OF:" at 12058.46,2569.71 h60
  text "X" at 11695.97,2441.08 h60
  text "ANSI IPC-A-600F CLASS ->" at 11823.96,2441.08 h60
  text "X" at 13471.97,2441.08 h60
  text "2" at 13581.96,2441.08 h60
  text "1" at 13266.96,2439.58 h60
  text "3" at 13935.96,2439.58 h60
  text "X" at 12507.97,2293.39 h60
  text "RoHS" at 12635.96,2293.39 h60
  text "OTHER" at 13280.36,2293.39 h60
  text "PER ORDER" at 13677.42,2293.39 h60
  text "ALL BOARDS MUST MEET OR EXCEED UL94-V0 REQUIREMENTS." at 11361,2139.57 h60
  text "PCB MUST BEAR THE UL94V-0 UL REGISTERED MATERIAL ID NUMBER" at 11361,2023.5 h60
  text "ADDITIONAL REQUIREMENTS:" at 11333.46,1854.08 h60
  text "MICROSECTION:" at 11408.23,1746.95 h60
  text "YES" at 12313.96,1746.95 h60
  text "REQUIRED" at 13175.46,1602.62 h60
  text "BARE BOARD ELEC. TEST:" at 11408.23,1599.76 h60
  text "NONE" at 12713.96,1599.76 h60
  text "X" at 13057.46,1599.76 h60
  text "PER ORDER" at 13767.46,1599.76 h60
  text "XX MIL VIAS REQUIRE NON-CONDUCTIVE FILL AND PLANARIZE" at 11576.38,1394.82 h59
  text "XX MIL VIAS REQUIRE CONDUCTIVE FILL AND PLANARIZE" at 11584.38,1290.84 h60
  text "OUTER XX MIL VIAS REQUIRE 50 OHM SINGLE-ENDED IMPEDANCE" at 11583.39,1127.46 h58
  text "LAYER 2 & 3 (INNER LAYERS) XX MIL WIDE, XX MIL SPACE / TRACES REQUIRE 100 OHM DIFFERENTIAL IMPEDANCE" at 11575.39,891.74 h60
  text ".Layer_Name" at 577,-858.49 h60
M11 Gerber Information:
  lines w10: -292,-930.17 6308,-930.17 ; -292,-726.83 6310,-726.83 ; -292,-523.5 -292,-1133.5 3713,-1133.5 6310,-1133.5 6310,-523.5 -291.5,-523.5 -291.5,-1133.5 1284,-1133.5 ; 2173,-1133.5 2173,-523.5 ; 3440,-726.83 3440,-523.5 ; 4280,-726.83 4280,-523.5 ; 4902,-1140 4902,-937.17
  text "ALL ARTWORK VIEWED FROM TOP SIDE" at -228.5,-655.67 h60
  text "BOARD #:" at 2248,-655.67 h60
  text ".PRJ_Number" at 2793.5,-655.67 h60
  text "REV:" at 3638,-655.67 h60
  text ".PCB_Rev" at 3929.5,-655.67 h60
  text "SVN REV:" at 4476,-655.67 h60
  text ".VersionControl_RevNumber" at 4982,-655.67 h60
  text "LAYER NAME =" at -228.5,-858.49 h60
  text "TID #:" at 2248,-859 h60
  text ".TID" at 2793.5,-859 h60
  text "PLOT NAME =" at -228.5,-1064.34 h60
  text ".plot_File_Name" at 577,-1064.34 h60
  text "GENERATED    :" at 2250,-1064.34 h60
  text ".Print_Date" at 3119.5,-1064.34 h60
  text ".Print_Time" at 3848.5,-1064.34 h60
  text "TEXAS INSTRUMENTS" at 5113,-1064.34 h60
M12 Stackup:
  drawing of 295 lines, arcs and shapes, not listed
  text "Layer" at 9797.84,7830 h60
  text "Name" at 10207.76,7830 h60
  text "Material" at 11137.5,7830 h60
  text "Thickness" at 11997.27,7830 h60
  text "Constant" at 12647.1,7830 h60
  text "Board Layer Stack" at 13216.96,7830 h60
  text "1" at 9797.84,7710 h60
  text "Top Overlay" at 10207.76,7710 h60
  text "2" at 9797.84,7590 h60
  text "Top Solder" at 10207.76,7590 h60
  text "Solder Resist" at 11137.5,7590 h60
  text "0.40mil" at 11997.27,7590 h60
  text "3.5" at 12647.1,7590 h60
  text "3" at 9797.84,7470 h60
  text "Top Layer" at 10207.76,7470 h60
  text "Copper" at 11137.5,7470 h60
  text "1.40mil" at 11997.27,7470 h60
  text "4" at 9797.84,7350 h60
  text "Dielectric 1" at 10207.76,7350 h60
  text "FR-4" at 11137.5,7350 h60
  text "8.00mil" at 11997.27,7350 h60
  text "4.2" at 12647.1,7350 h60
  text "5" at 9797.84,7230 h60
  text "Power" at 10207.76,7230 h60
  text "Copper" at 11137.5,7230 h60
  text "1.40mil" at 11997.27,7230 h60
  text "6" at 9797.84,7110 h60
  text "Dielectric 2" at 10207.76,7110 h60
  text "FR-4" at 11137.5,7110 h60
  text "40.00mil" at 11997.27,7110 h60
  text "4.2" at 12647.1,7110 h60
  text "7" at 9797.84,6990 h60
  text "Ground" at 10207.76,6990 h60
  text "Copper" at 11137.5,6990 h60
  text "1.40mil" at 11997.27,6990 h60
  text "8" at 9797.84,6870 h60
  text "Dielectric 3" at 10207.76,6870 h60
  text "FR-4" at 11137.5,6870 h60
  text "8.00mil" at 11997.27,6870 h60
  text "4.2" at 12647.1,6870 h60
  text "9" at 9797.84,6750 h60
  text "Bottom Layer" at 10207.76,6750 h60
  text "Copper" at 11137.5,6750 h60
  text "1.40mil" at 11997.27,6750 h60
  text "10" at 9797.84,6630 h60
  text "Bottom Solder" at 10207.76,6630 h60
  text "Solder Resist" at 11137.5,6630 h60
  text "0.40mil" at 11997.27,6630 h60
  text "3.5" at 12647.1,6630 h60
  text "11" at 9797.84,6510 h60
  text "Bottom Overlay" at 10207.76,6510 h60
  text ".Layer_Name" at 577,-858.49 h60
M13 Component Bodies Top:
  text ".Layer_Name" at 577,-858.49 h60
M14 Component Bodies Bottom:
  text ".Layer_Name" at 577,-858.49 h60
M15 Courtyards Top:
  text ".Layer_Name" at 577,-858.49 h60
M16 Courtyards Bottom:
  text ".Layer_Name" at 577,-858.49 h60
Drill Drawing:
  circle w10: c5363.54,2522.56 r16.54
  circle w10: c5363.54,2522.56 r27.56
  lines w10: 5335.98,2426.09 5391.1,2426.09 5363.54,2370.97 5335.98,2426.09 ; 5335.98,2646.58 5363.54,2619.02 5391.1,2646.58 5363.54,2674.14 5335.98,2646.58 ; 5335.98,2756.83 5349.76,2756.83 5363.54,2743.05 5377.32,2756.83 5391.1,2756.83 5377.32,2770.61 5391.1,2784.39 5377.32,2784.39 5363.54,2798.17 5349.76,2784.39 5335.98,2784.39 5349.76,2770.61 5335.98,2756.83 ; 5335.98,2867.07 5363.54,2880.86 5391.1,2867.07 5377.32,2894.64 5391.1,2922.2 5363.54,2908.42 5335.98,2922.2 5349.76,2894.64 5335.98,2867.07 ; 5335.98,3004.88 5349.76,3004.88 5349.76,2991.1 5377.32,2991.1 5377.32,3004.88 5391.1,3004.88 5391.1,3032.44 5377.32,3032.44 5377.32,3046.22 5349.76,3046.22 5349.76,3032.44 5335.98,3032.44 5335.98,3004.88 ; 5335.98,3170.25 5391.1,3170.25 5363.54,3115.13 5335.98,3170.25 ; 5335.98,3239.15 5391.1,3239.15 5391.1,3294.28 5335.98,3294.28 5335.98,3239.15 ; 5347,2762.34 5355.27,2762.34 5363.54,2754.07 5371.81,2762.34 5380.08,2762.34 5371.81,2770.61 5380.08,2778.88 5371.81,2778.88 5363.54,2787.15 5355.27,2778.88 5347,2778.88 5355.27,2770.61 5347,2762.34 ; 5347,2878.1 5363.54,2886.37 5380.08,2878.1 5371.81,2894.64 5380.08,2911.17 5363.54,2902.9 5347,2911.17 5355.27,2894.64 5347,2878.1 ; 5347,3159.23 5380.08,3159.23 5363.54,3126.15 5347,3159.23
  lines w12: 5286,2333.76 8512.8,2333.76 ; 5286,3325.97 8512.8,3325.97 ; 5623.36,2209.73 5623.36,3450 ; 5955.06,2209.73 5955.06,3450 ; 6590.91,2209.73 6590.91,3450 ; 6849.71,2209.73 6849.71,3450 ; 7224.46,2209.73 7224.46,3450 ; 7947,2209.73 7947,3450 ; 5286,2209.73 8512.8,2209.73 8512.8,3450 5286,3450 5286,2209.73
  text "Symbol" at 5360.42,3363.18 h72
  text "Quantity" at 5660.57,3363.18 h72
  text "Finished Hole Size" at 5992.26,3363.18 h72
  text "Plated" at 6628.12,3363.18 h72
  text "Hole Type" at 6886.92,3363.18 h72
  text "Drill Layer Pair" at 7261.67,3363.18 h72
  text "Hole Tolerance" at 7984.21,3363.18 h72
  text "61" at 5660.57,3239.15 h60
  text "16.00mil (0.406mm)" at 5992.26,3239.15 h60
  text "PTH" at 6628.12,3239.15 h60
  text "Round" at 6886.92,3239.15 h60
  text "Top Layer - Bottom Layer" at 7261.67,3239.15 h60
  text "3" at 5660.57,3115.13 h60
  text "31.50mil (0.800mm)" at 5992.26,3115.13 h60
  text "PTH" at 6628.12,3115.13 h60
  text "Round" at 6886.92,3115.13 h60
  text "Top Layer - Bottom Layer" at 7261.67,3115.13 h60
  text "+/-7.87mil" at 7984.21,3115.13 h60
  text "2" at 5660.57,2991.1 h60
  text "40.00mil (1.016mm)" at 5992.26,2991.1 h60
  text "PTH" at 6628.12,2991.1 h60
  text "Round" at 6886.92,2991.1 h60
  text "Top Layer - Bottom Layer" at 7261.67,2991.1 h60
  text "40" at 5660.57,2867.07 h60
  text "40.16mil (1.020mm)" at 5992.26,2867.07 h60
  text "PTH" at 6628.12,2867.07 h60
  text "Round" at 6886.92,2867.07 h60
  text "Top Layer - Bottom Layer" at 7261.67,2867.07 h60
  text "6" at 5660.57,2743.05 h60
  text "51.18mil (1.300mm)" at 5992.26,2743.05 h60
  text "PTH" at 6628.12,2743.05 h60
  text "Round" at 6886.92,2743.05 h60
  text "Top Layer - Bottom Layer" at 7261.67,2743.05 h60
  text "+/-7.87mil" at 7984.21,2743.05 h60
  text "12" at 5660.57,2619.02 h60
  text "51.18mil (1.300mm)" at 5992.26,2619.02 h60
  text "PTH" at 6628.12,2619.02 h60
  text "Round" at 6886.92,2619.02 h60
  text "Top Layer - Bottom Layer" at 7261.67,2619.02 h60
  text "16" at 5660.57,2494.99 h60
  text "63.00mil (1.600mm)" at 5992.26,2494.99 h60
  text "PTH" at 6628.12,2494.99 h60
  text "Round" at 6886.92,2494.99 h60
  text "Top Layer - Bottom Layer" at 7261.67,2494.99 h60
  text "6" at 5660.57,2370.97 h60
  text "125.98mil (3.200mm)" at 5992.26,2370.97 h60
  text "PTH" at 6628.12,2370.97 h60
  text "Round" at 6886.92,2370.97 h60
  text "Top Layer - Bottom Layer" at 7261.67,2370.97 h60
  text "146 Total" at 5660.57,2246.94 h60
  text ".Layer_Name" at 577,-858.49 h60
Mechanical 17:
  lines w10: 2000,0 2000,4300 ; 2010,4320 2440,4750 2800,4750
  text "V-Groove" at 2460,4790 h72.83
  text ".Layer_Name" at 577,-858.49 h60
Mechanical 18:
  text ".Layer_Name" at 577,-858.49 h60
Mechanical 19:
  text ".Layer_Name" at 577,-858.49 h60

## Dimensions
0,-400 to 1000,-400 on M2 Board Dimensions
0,0 to 5000,0 on M2 Board Dimensions
0,0 to 0,4300 on M2 Board Dimensions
